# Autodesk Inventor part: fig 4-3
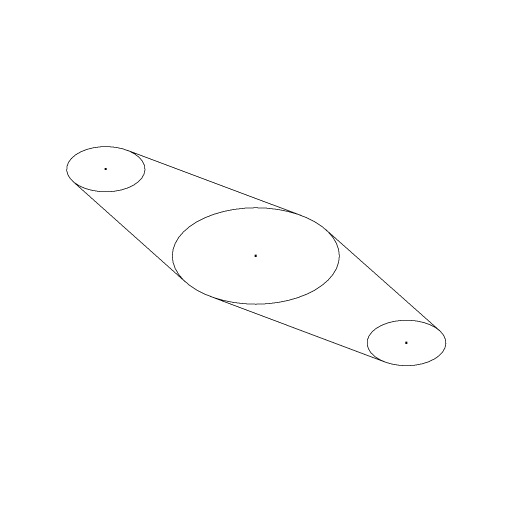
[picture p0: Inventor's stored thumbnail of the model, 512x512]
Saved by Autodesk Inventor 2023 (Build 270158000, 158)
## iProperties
Created: 2005-02
Part Number: fig 4-3
Document SubType Name: Modeling
Designer: CADCIM
Manufacturer: Standard
Standards Organization: Custom
Density: 1 g/cm^3
Material: Generic
Appearance: Default
Author: CADCIM
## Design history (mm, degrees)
sketch "Sketch1"
  geometry: L1 (-33.874, 5.844)-(-2.722, 12.469); L2 (2.595, 12.472)-(33.871, 5.852); L3 (-33.884, -5.902)-(-2.745, -12.585); L4 (2.595, -12.592)-(33.871, -5.972); A1 r 12.81 centre (-0.057, -0.06) between (-2.722, 12.469) and (2.595, 12.472); A2 r 6.006 centre (-32.624, -0.03) between (-33.874, 5.844) and (-33.884, -5.902); A3 r 6.043 centre (32.619, -0.06) between (33.871, 5.852) and (33.871, -5.972)
  constraints: 8 end point, 8 point on circle, 8 tangent, 3 centre point, 1 other
